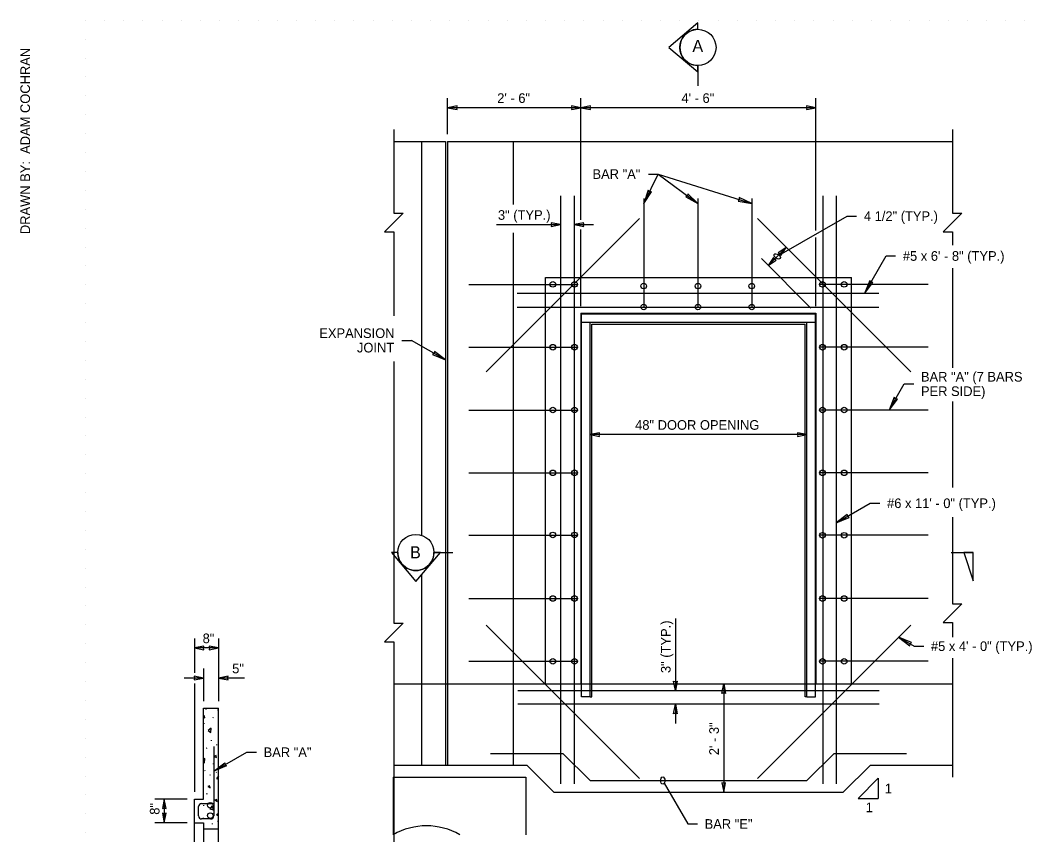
# Model space of a CAD drawing. Extents: x 99862 to 103151, y 100000 to 102076.
# Drawn here: x 99892 to 101571, y 100723 to 102075 of the extents above; entities that cross this region are included whole.
import ezdxf

# ---------------------------------------------------------------- set-up
doc = ezdxf.new("R2010")
doc.units = 0
for name, color, linetype in [('Level 1', 7, 'Continuous'), ('Level 13', 7, 'Continuous'), ('Level 15', 7, 'Continuous'), ('Level 16', 7, 'Continuous'), ('Level 17', 7, 'Continuous'), ('Level 20', 7, 'Continuous'), ('Level 5', 7, 'Continuous'), ('Level 62', 7, 'Continuous'), ('Level 9', 7, 'Continuous')]:
    doc.layers.add(name, color=color, linetype=linetype)

msp = doc.modelspace()

# ---------------------------------------------------------------- linework, layer by layer
at = {"layer": 'Level 1'}
for p, q in [((100000, 102075), (100000, 102075)), ((100031.8, 102075), (100031.8, 102075)), ((100063.6, 102075), (100063.6, 102075)), ((100095.5, 102075), (100095.5, 102075)), ((100127.3, 102075), (100127.3, 102075)), ((100159.1, 102075), (100159.1, 102075)), ((100190.9, 102075), (100190.9, 102075)), ((100222.7, 102075), (100222.7, 102075)), ((100254.5, 102075), (100254.5, 102075)), ((100286.4, 102075), (100286.4, 102075)), ((100318.2, 102075), (100318.2, 102075)), ((100350, 102075), (100350, 102075)), ((100381.8, 102075), (100381.8, 102075)), ((100413.6, 102075), (100413.6, 102075)), ((100445.5, 102075), (100445.5, 102075)), ((100477.3, 102075), (100477.3, 102075)), ((100509.1, 102075), (100509.1, 102075)), ((100540.9, 102075), (100540.9, 102075)), ((100572.7, 102075), (100572.7, 102075)), ((100604.5, 102075), (100604.5, 102075)), ((100636.4, 102075), (100636.4, 102075)), ((100668.2, 102075), (100668.2, 102075)), ((100700, 102075), (100700, 102075)), ((100731.8, 102075), (100731.8, 102075)), ((100763.6, 102075), (100763.6, 102075)), ((100795.5, 102075), (100795.5, 102075)), ((100827.3, 102075), (100827.3, 102075)), ((100859.1, 102075), (100859.1, 102075)), ((100890.9, 102075), (100890.9, 102075)), ((100922.7, 102075), (100922.7, 102075)), ((100954.5, 102075), (100954.5, 102075)), ((100986.4, 102075), (100986.4, 102075)), ((101018.2, 102075), (101018.2, 102075)), ((101050, 102075), (101050, 102075)), ((101081.8, 102075), (101081.8, 102075)), ((101113.6, 102075), (101113.6, 102075)), ((101145.5, 102075), (101145.5, 102075)), ((101177.3, 102075), (101177.3, 102075)), ((101209.1, 102075), (101209.1, 102075)), ((101240.9, 102075), (101240.9, 102075)), ((101272.7, 102075), (101272.7, 102075)), ((101304.5, 102075), (101304.5, 102075)), ((101336.4, 102075), (101336.4, 102075)), ((101368.2, 102075), (101368.2, 102075)), ((101400, 102075), (101400, 102075)), ((101431.8, 102075), (101431.8, 102075)), ((101463.6, 102075), (101463.6, 102075)), ((101495.5, 102075), (101495.5, 102075)), ((101527.3, 102075), (101527.3, 102075)), ((101559.1, 102075), (101559.1, 102075)), ((100000, 102043.6), (100000, 102043.6)), ((100000, 102012.3), (100000, 102012.3)), ((100000, 101980.9), (100000, 101980.9)), ((100000, 101949.6), (100000, 101949.6)), ((100000, 101918.2), (100000, 101918.2)), ((100000, 101886.9), (100000, 101886.9)), ((100000, 101855.5), (100000, 101855.5)), ((100000, 101824.2), (100000, 101824.2)), ((100000, 101792.8), (100000, 101792.8)), ((100000, 101761.4), (100000, 101761.4)), ((100000, 101730.1), (100000, 101730.1)), ((100000, 101698.7), (100000, 101698.7)), ((100000, 101667.4), (100000, 101667.4)), ((100000, 101636), (100000, 101636)), ((100000, 101604.7), (100000, 101604.7)), ((100000, 101573.3), (100000, 101573.3)), ((100000, 101541.9), (100000, 101541.9)), ((100000, 101510.6), (100000, 101510.6)), ((100000, 101479.2), (100000, 101479.2)), ((100000, 101447.9), (100000, 101447.9)), ((100000, 101416.5), (100000, 101416.5)), ((100000, 101385.2), (100000, 101385.2)), ((100000, 101353.8), (100000, 101353.8)), ((100000, 101322.5), (100000, 101322.5)), ((100000, 101291.1), (100000, 101291.1)), ((100000, 101259.7), (100000, 101259.7)), ((100000, 101228.4), (100000, 101228.4)), ((100000, 101197), (100000, 101197)), ((100000, 101165.7), (100000, 101165.7)), ((100000, 101134.3), (100000, 101134.3)), ((100000, 101103), (100000, 101103)), ((100000, 101071.6), (100000, 101071.6)), ((100000, 101040.3), (100000, 101040.3)), ((100000, 101008.9), (100000, 101008.9)), ((100000, 100977.5), (100000, 100977.5)), ((100000, 100946.2), (100000, 100946.2)), ((100000, 100914.8), (100000, 100914.8)), ((100000, 100883.5), (100000, 100883.5)), ((100000, 100852.1), (100000, 100852.1)), ((100000, 100820.8), (100000, 100820.8)), ((100000, 100789.4), (100000, 100789.4)), ((100000, 100758.1), (100000, 100758.1)), ((100000, 100726.7), (100000, 100726.7))]:
    msp.add_line(p, q, dxfattribs=at)
at = {"layer": 'Level 13'}
for p, q in [((100788.6, 101783.8), (100788.6, 100807.9)), ((100811.1, 101783.8), (100811.1, 100807.9)), ((101223.6, 101783.8), (101223.6, 100807.9)), ((101246.1, 101783.8), (101246.1, 100807.9)), ((101316.5, 101621.6), (100716.5, 101621.6)), ((100716.5, 101599.1), (101316.5, 101599.1)), ((100717.4, 100962.5), (101317.4, 100962.5)), ((101317.4, 100940), (100717.4, 100940)), ((100212.8, 100870), (100212.8, 100754.6)), ((100187.8, 100754.6), (100187.8, 100770)), ((100192.8, 100775), (100210.5, 100775)), ((100207.8, 100749.6), (100192.8, 100749.6))]:
    msp.add_line(p, q, dxfattribs=at)
for points in [[(100926.5, 101779.1), (100926.5, 101599.1)], [(101016.5, 101779.1), (101016.5, 101599.1)], [(101105.8, 101779.1), (101105.8, 101599.1)], [(100665.1, 101491.5), (100919.7, 101746.1)], [(101115.1, 101746.1), (101369.7, 101491.5)], [(100636.4, 101636.7), (100816.4, 101636.7)], [(101398.4, 101636.7), (101218.4, 101636.7)], [(100636.4, 101532.4), (100816.4, 101532.4)], [(101398.4, 101532.4), (101218.4, 101532.4)], [(100636.4, 101428.2), (100816.4, 101428.2)], [(101398.4, 101428.2), (101218.4, 101428.2)], [(100636.4, 101323.9), (100816.4, 101323.9)], [(101398.4, 101323.9), (101218.4, 101323.9)], [(100636.4, 101220.4), (100816.4, 101220.4)], [(101398.4, 101220.4), (101218.4, 101220.4)], [(100636.4, 101115.4), (100816.4, 101115.4)], [(101398.4, 101115.4), (101218.4, 101115.4)], [(100665.1, 101071), (100919.7, 100816.5)], [(101115.1, 100816.5), (101369.7, 101071)], [(100636.4, 101011.2), (100816.4, 101011.2)], [(101398.4, 101011.2), (101218.4, 101011.2)], [(100672.4, 100858.3), (100792.4, 100858.3), (100837.4, 100813.3), (101197.4, 100813.3), (101242.4, 100858.3), (101362.4, 100858.3)]]:
    msp.add_lwpolyline(points, dxfattribs=at)
for centre in [(100775.6, 101636.7), (100811.7, 101636.7), (100926.5, 101633.9), (101016.5, 101633.9), (101105.8, 101633.9), (101223.1, 101636.7), (101259.2, 101636.7), (100926.5, 101599.1), (101016.5, 101599.1), (101105.8, 101599.1), (100775.6, 101532.4), (100811.7, 101532.4), (101223.1, 101532.4), (101259.2, 101532.4), (100775.6, 101428.2), (100811.7, 101428.2), (101223.1, 101428.2), (101259.2, 101428.2), (100775.6, 101323.9), (100811.7, 101323.9), (101223.1, 101323.9), (101259.2, 101323.9), (100775.6, 101220.9), (100811.7, 101220.9), (101223.1, 101220.4), (101259.2, 101220.4), (100775.6, 101115.4), (100811.7, 101115.4), (101223.1, 101115.4), (101259.2, 101115.4), (100775.6, 101011.2), (100811.7, 101011.2), (101223.1, 101011.2), (101259.2, 101011.2), (100207.2, 100772.3), (100207.2, 100755.2)]:
    msp.add_circle(centre, 4.63, dxfattribs=at)
for centre, start, end in [((100192.8, 100770), 90, 180), ((100192.8, 100754.6), 180, 270), ((100207.8, 100754.6), 270, 0)]:
    msp.add_arc(centre, 5, start, end, dxfattribs=at)
at = {"layer": 'Level 15'}
for p, q in [((100601.1, 101885.8), (100601.1, 101945.8)), ((100822.4, 101744), (100822.4, 101945.8)), ((101212.4, 101726.2), (101212.4, 101945.8)), ((100822.4, 101929.8), (100601.1, 101929.8)), ((101212.4, 101929.8), (100822.4, 101929.8)), ((101151.4, 101684.9), (101263.9, 101749.9)), ((101263.9, 101749.9), (101279.9, 101749.9)), ((100682.2, 101735.8), (100788.6, 101735.8)), ((100811.1, 101735.8), (100843.1, 101735.8)), ((100822.4, 101600.8), (100822.4, 101727.6)), ((101212.4, 101600.8), (101212.4, 101714.2)), ((101292.7, 101621.6), (101328.6, 101683.8)), ((101328.6, 101683.8), (101344.6, 101683.8)), ((100525.1, 101543.7), (100541.1, 101543.7)), ((100597.4, 101511.2), (100541.1, 101543.7)), ((101333.6, 101428.2), (101358.6, 101471.4)), ((101358.6, 101471.4), (101374.6, 101471.4)), ((101197.4, 101387.4), (100837.4, 101387.4)), ((101246.1, 101241), (101302.4, 101273.5)), ((101302.4, 101273.5), (101318.4, 101273.5)), ((100979.1, 101082), (100979.1, 100962.5)), ((100180.9, 101049.3), (100180.9, 100992.2)), ((100220.9, 101049.3), (100220.9, 100945.3)), ((101349.6, 101051), (101375.2, 101036.3)), ((100220.9, 101033.3), (100180.9, 101033.3)), ((101375.2, 101036.3), (101391.2, 101036.3)), ((100195.9, 100999.3), (100195.9, 100945.3)), ((100195.9, 100983.3), (100163.9, 100983.3)), ((100263.9, 100983.3), (100220.9, 100983.3)), ((100180.9, 100974.3), (100180.9, 100794.7)), ((101059.2, 100973.8), (101059.2, 100793.8)), ((100979.1, 100940), (100979.1, 100908)), ((100212.8, 100828.7), (100267.7, 100860.3)), ((100267.7, 100860.3), (100283.7, 100860.3)), ((100960.5, 100809), (100999.6, 100741.3)), ((101315.8, 100817.2), (101315.8, 100783.8)), ((100168.9, 100782.7), (100114.9, 100782.7)), ((100130.9, 100782.7), (100130.9, 100743.3)), ((100168.9, 100743.3), (100114.9, 100743.3)), ((100999.6, 100741.3), (101015.6, 100741.3))]:
    msp.add_line(p, q, dxfattribs=at)
for points in [[(100601.1, 101929.8), (100616.9, 101926.7), (100616.1, 101929.8), (100616.9, 101932.9)], [(100822.4, 101929.8), (100806.7, 101932.9), (100807.4, 101929.8), (100806.7, 101926.7)], [(100822.4, 101929.8), (100838.1, 101926.7), (100837.4, 101929.8), (100838.1, 101932.9)], [(101212.4, 101929.8), (101196.7, 101932.9), (101197.4, 101929.8), (101196.7, 101926.7)], [(100926.5, 101771), (100939.2, 101790.2), (100936.1, 101790.5), (100933.9, 101792.8)], [(101016.5, 101771), (100999.9, 101786.9), (100999, 101783.9), (100996.4, 101782.1)], [(101105.8, 101771), (101084.9, 101780.6), (101085, 101777.5), (101083.1, 101775)], [(100788.6, 101735.8), (100772.9, 101738.9), (100773.6, 101735.8), (100772.9, 101732.7)], [(100811.1, 101735.8), (100826.9, 101732.7), (100826.1, 101735.8), (100826.9, 101738.9)], [(101163.1, 101698.1), (101149.8, 101689.1), (101152.5, 101687.4), (101154.2, 101684.8)], [(101133.1, 101668.1), (101146.4, 101677), (101143.7, 101678.7), (101142.1, 101681.4)], [(101292.7, 101621.6), (101306.7, 101639.9), (101303.5, 101640.5), (101301.5, 101642.9)], [(100597.4, 101511.2), (100579.1, 101525.2), (100578.5, 101522.1), (100576.1, 101520.1)], [(101333.6, 101428.2), (101347.6, 101446.4), (101344.5, 101447), (101342.4, 101449.4)], [(100837.4, 101387.4), (100853.1, 101384.3), (100852.4, 101387.4), (100853.1, 101390.5)], [(101197.4, 101387.4), (101181.7, 101390.5), (101182.4, 101387.4), (101181.7, 101384.3)], [(101246.1, 101241), (101267.4, 101249.8), (101265, 101251.8), (101264.4, 101255)], [(101349.6, 101051), (101367.9, 101037), (101368.5, 101040.1), (101370.9, 101042.2)], [(100180.9, 101033.3), (100196.6, 101030.2), (100195.9, 101033.3), (100196.6, 101036.3)], [(100220.9, 101033.3), (100205.2, 101036.3), (100205.9, 101033.3), (100205.2, 101030.2)], [(100195.9, 100983.3), (100180.2, 100986.3), (100180.9, 100983.3), (100180.2, 100980.2)], [(100220.9, 100983.3), (100236.6, 100980.2), (100235.9, 100983.3), (100236.6, 100986.3)], [(100979.1, 100962.5), (100976, 100978.2), (100979.1, 100977.5), (100982.2, 100978.2)], [(101059.2, 100973.8), (101062.2, 100958), (101059.2, 100958.8), (101056.1, 100958)], [(100979.1, 100940), (100982.2, 100924.3), (100979.1, 100925), (100976, 100924.3)], [(100212.8, 100828.7), (100231.1, 100842.7), (100231.7, 100839.5), (100234.1, 100837.5)], [(101059.2, 100793.8), (101062.2, 100809.5), (101059.2, 100808.8), (101056.1, 100809.5)], [(100130.9, 100782.7), (100127.8, 100767), (100130.9, 100767.7), (100134, 100767)], [(100130.9, 100743.3), (100134, 100759), (100130.9, 100758.3), (100127.8, 100759)]]:
    msp.add_lwpolyline(points, close=True, dxfattribs=at)
for points in [[(100511.7, 101893.8), (100511.7, 101754.6), (100527.2, 101754.6), (100496.2, 101723.6), (100511.7, 101723.6), (100511.7, 101584.4)], [(101439.1, 101893.8), (101439.1, 101754.6), (101454.6, 101754.6), (101423.7, 101723.6), (101439.1, 101723.6), (101439.1, 101702)], [(100926.5, 101771), (100950.3, 101819.7), (101016.5, 101771)], [(100934.3, 101819.7), (100950.3, 101819.7), (101105.8, 101771)], [(101163.1, 101698.1), (101133.1, 101668.1)], [(101121.8, 101679.4), (101203.9, 101597.3)], [(101439.1, 101663.6), (101439.1, 101498.2)], [(100511.7, 101508.6), (100511.7, 101074.6), (100527.2, 101074.6), (100496.2, 101043.6), (100511.7, 101043.6), (100511.7, 100683.8)], [(101439.1, 101442.3), (101439.1, 101299.5)], [(101439.1, 101250.5), (101439.1, 101106.6), (101454.6, 101106.6), (101423.7, 101075.7), (101439.1, 101075.7), (101439.1, 101051.3)], [(101439.1, 101016.3), (101439.1, 100818.8)], [(101282.4, 100783.8), (101315.8, 100817.2)], [(101282.4, 100783.8), (101315.8, 100783.8)]]:
    msp.add_lwpolyline(points, dxfattribs=at)
for centre, major_axis in [((101148.1, 101683.1), (-5.01, 3.3)), ((100958.1, 100813.3), (0, -6))]:
    msp.add_ellipse(centre, major_axis=major_axis, ratio=0.57735, dxfattribs=at)
at = {"layer": 'Level 16'}
for p, q in [((100200.5, 100931.1), (100200.2, 100932.3)), ((100220, 100929.6), (100219.8, 100930.8)), ((100211.9, 100917.7), (100211.2, 100917)), ((100197.1, 100908.6), (100196.7, 100907.5)), ((100209.3, 100879.3), (100209.1, 100880.5)), ((100201.2, 100867.3), (100200.5, 100866.7)), ((100218, 100871.9), (100217.8, 100873.1)), ((100198.6, 100829), (100198.4, 100830.2)), ((100212.7, 100840.7), (100212.4, 100841.9)), ((100217.6, 100827.4), (100217, 100826.8)), ((100207.3, 100821.5), (100207.1, 100822.7)), ((100202, 100790.4), (100201.7, 100791.6)), ((100206.9, 100777.1), (100206.3, 100776.5)), ((100196.6, 100771.2), (100196.4, 100772.4)), ((100210.8, 100741.1), (100210.6, 100742.3)), ((100219.8, 100746), (100219.4, 100744.9))]:
    msp.add_line(p, q, dxfattribs=at)
for points in [[(100198.4, 100917.2), (100197.6, 100920.6), (100195.9, 100919.8)], [(100195.9, 100918.6), (100198.4, 100917.2)], [(100208.3, 100892.9), (100208.8, 100900.1), (100203.5, 100896.5), (100208.2, 100893)], [(100197.6, 100842.6), (100198.1, 100849.8), (100195.9, 100848.3)], [(100195.9, 100843.9), (100197.5, 100842.7)], [(100217.5, 100851.5), (100216.7, 100854.8), (100213.8, 100853.5), (100217.5, 100851.5)], [(100220.9, 100821.4), (100217.3, 100816.5), (100220.9, 100815.4)], [(100206.8, 100801.1), (100206, 100804.5), (100203.2, 100803.2), (100206.8, 100801.1)], [(100218.6, 100778.7), (100217.8, 100782.1), (100214.9, 100780.8), (100218.6, 100778.7)], [(100212.4, 100764.5), (100210.4, 100771.3), (100206.6, 100766.2), (100212.2, 100764.5)], [(100196.1, 100750.8), (100195.9, 100751.6)], [(100195.9, 100750.9), (100196.1, 100750.8)], [(100220.9, 100755.5), (100220.3, 100757.9), (100217.5, 100756.6), (100220.9, 100754.7)]]:
    msp.add_lwpolyline(points, dxfattribs=at)
at = {"layer": 'Level 17'}
for p, q in [((100511.7, 101873.8), (100597.4, 101873.8)), ((100557.8, 101873.8), (100557.8, 101220.4)), ((100597.4, 101873.8), (100597.4, 100973.8)), ((100601.1, 101873.8), (100601.1, 100973.8)), ((100601.1, 101873.8), (101439.1, 101873.8)), ((100709.7, 101873.8), (100709.7, 101769.3)), ((100709.7, 101722), (100709.7, 100838.8)), ((100763.3, 101647.9), (101271.5, 101647.9)), ((100763.3, 100973.8), (100763.3, 101647.9)), ((101271.5, 100973.8), (101271.5, 101647.9)), ((100822.4, 101588.8), (101212.4, 101588.8)), ((100822.4, 101588.8), (100822.4, 100973.8)), ((101212.4, 101588.8), (101212.4, 100973.8)), ((100557.8, 101154.8), (100557.8, 100838.8)), ((100511.7, 100973.8), (101439.1, 100973.8)), ((100597.4, 100973.8), (100597.4, 100838.8)), ((100601.1, 100973.8), (100601.1, 100838.8)), ((100195.9, 100933.3), (100220.9, 100933.3)), ((100195.9, 100782.7), (100195.9, 100933.3)), ((100220.9, 100733.3), (100220.9, 100933.3)), ((100511.7, 100838.8), (100732.4, 100838.8)), ((101302.6, 100838.8), (101439.1, 100838.8)), ((100510.9, 100818.7), (100510.9, 100723.4)), ((100180.9, 100743.3), (100180.9, 100782.7)), ((100180.9, 100782.7), (100195.9, 100782.7)), ((100220.9, 100333.3), (100220.9, 100733.3))]:
    msp.add_line(p, q, dxfattribs=at)
for points in [[(100732.4, 100838.8), (100777.4, 100793.8), (101257.6, 100793.8), (101302.6, 100838.8)], [(100510.9, 100818.7), (100731.1, 100818.7), (100731.1, 100723.4)], [(100180.9, 100743.3), (100195.9, 100743.3), (100195.9, 100733.3)], [(100195.9, 100333.3), (100180.9, 100333.3), (100180.9, 100743.3)], [(100195.9, 100733.3), (100220.9, 100733.3)], [(100195.9, 100733.3), (100195.9, 100333.3)]]:
    msp.add_lwpolyline(points, dxfattribs=at)
msp.add_arc((100566, 100628.1), 110.1, 60, 120, dxfattribs=at)
at = {"layer": 'Level 5'}
for p, q in [((100823.3, 101573.8), (100823.3, 101587.9)), ((100823.3, 101587.9), (101211.5, 101587.9)), ((101211.5, 101573.8), (101211.5, 101587.9)), ((100823.3, 101573.8), (101197.4, 101573.8)), ((100823.3, 100952.4), (100823.3, 101573.8)), ((100837.4, 100952.4), (100837.4, 101573.8)), ((100840.2, 101570.9), (101194.6, 101570.9)), ((100840.2, 100952.4), (100840.2, 101570.9)), ((101194.6, 100952.4), (101194.6, 101570.9)), ((101197.4, 101573.8), (101211.5, 101573.8)), ((101197.4, 100952.4), (101197.4, 101573.8)), ((101211.5, 100952.4), (101211.5, 101573.8)), ((100837.4, 100952.4), (100823.3, 100952.4)), ((100837.4, 100952.3), (100840.2, 100952.4)), ((100837.4, 100952.4), (100837.4, 100952.3)), ((101197.4, 100952.4), (101194.6, 100952.4)), ((101197.4, 100952.4), (101211.5, 100952.4))]:
    msp.add_line(p, q, dxfattribs=at)
at = {"layer": 'Level 9'}
for p, q in [((101016.5, 102070.5), (100968, 102029.9)), ((101016.5, 102059.9), (101016.5, 102070.5)), ((100968, 102029.9), (101016.5, 101989.3)), ((101016.5, 101989.3), (101016.5, 101999.9)), ((101016.5, 101999.9), (101016.5, 101966)), ((100518.4, 101191.9), (100507.8, 101191.9)), ((100507.8, 101191.9), (100548.4, 101143.5)), ((100548.4, 101143.5), (100589, 101191.9)), ((100589, 101191.9), (100578.4, 101191.9)), ((100579.9, 101191.9), (100609.9, 101191.9)), ((101436.7, 101191.9), (101473.2, 101191.9))]:
    msp.add_line(p, q, dxfattribs=at)
msp.add_lwpolyline([(101457.7, 101191.9), (101473.2, 101145), (101473.2, 101191.9)], close=True, dxfattribs=at)
for centre in [(101016.5, 102029.9), (100548.4, 101191.9)]:
    msp.add_circle(centre, 30, dxfattribs=at)
for centre, start, end in [((101016.5, 102029.9), 89.9978, 270.0022), ((100548.4, 101191.9), 179.9978, 0.0022)]:
    msp.add_arc(centre, 30, start, end, dxfattribs=at)

# ---------------------------------------------------------------- texts
at = {"layer": 'Level 20'}
for s, height, rotation, p in [('A', 20, 360, (101007.3, 102022.3)), ('3" (TYP.)', 16, 90, (100971.1, 100991.7)), ('2\' - 3"', 16, 90, (101051.2, 100855.4)), ('8"', 16, 90, (100122.9, 100756.6))]:
    msp.add_text(s, height=height, rotation=rotation, dxfattribs=at).set_placement(p)
for s, height, p in [('2\' - 6"', 16, (100683.4, 101937.8)), ('4\' - 6"', 16, (100989.1, 101937.8)), ('BAR "A"', 16, (100841.5, 101811.7)), ('3" (TYP.)', 16, (100684.6, 101743.8)), ('4 1/2" (TYP.)', 16, (101291.9, 101741.9)), ('#5 x 6\' - 8" (TYP.)', 16, (101356.6, 101675.8)), ('EXPANSION', 16, (100388.1, 101547.7)), ('JOINT', 16, (100450.6, 101523.7)), ('BAR "A" (7 BARS', 16, (101386.6, 101475.4)), ('PER SIDE)', 16, (101386.6, 101451.4)), ('48" DOOR OPENING', 16, (100912.3, 101395.4)), ('#6 x 11\' - 0" (TYP.)', 16, (101330.4, 101265.5)), ('B', 20, (100538.7, 101182.1)), ('8"', 16, (100194.5, 101041.3)), ('#5 x 4\' - 0" (TYP.)', 16, (101403.2, 101028.3)), ('5"', 16, (100243.5, 100991.3)), ('BAR "A"', 16, (100295.7, 100852.3)), ('1', 16, (101326.6, 100792.2)), ('1', 16, (101294.8, 100760.8)), ('BAR "E"', 16, (101027.6, 100733.3))]:
    msp.add_text(s, height=height, dxfattribs=at).set_placement(p)
at = {"layer": 'Level 62'}
msp.add_text('DRAWN BY:  ADAM COCHRAN', height=16, rotation=90, dxfattribs=at).set_placement((99908, 101720.1))

doc.saveas('drawing.dxf')
